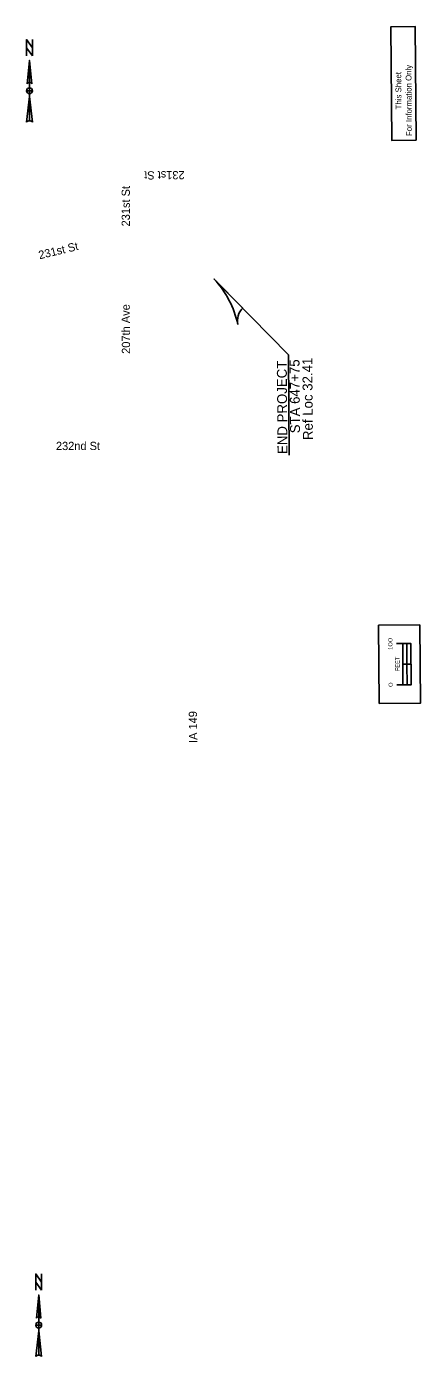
# Model space of a CAD drawing. Extents: x 23417754 to 23421386, y 6737896 to 6790956.
# Drawn here: x 23420298 to 23421255, y 6787728 to 6790956 of the extents above; entities that cross this region are included whole.
import ezdxf

# ---------------------------------------------------------------- set-up
doc = ezdxf.new("R2010")
doc.units = 0
for name, color, linetype in [('Curb', 7, 'Continuous'), ('Default', 7, 'Continuous'), ('dsnCellElements', 7, 'Continuous'), ('TextAlignmentLrg', 7, 'Continuous')]:
    doc.layers.add(name, color=color, linetype=linetype)

msp = doc.modelspace()

# ---------------------------------------------------------------- linework, layer by layer
at = {"layer": 'Curb'}
for p, q in [((23420305.1, 6790873.3), (23420310.8, 6790816.9)), ((23420305.1, 6790873.3), (23420305.1, 6790726.8)), ((23420299.5, 6790816.9), (23420299.5, 6790816.9)), ((23420299.7, 6790817.5), (23420300.8, 6790818.6)), ((23420298.1, 6790724), (23420305.1, 6790785.9)), ((23420305.1, 6790793), (23420305.1, 6790793)), ((23421231.8, 6789408.3), (23421211.8, 6789408.1)), ((23421231.8, 6789408.3), (23421211.8, 6789408.1))]:
    msp.add_line(p, q, dxfattribs=at)
for points in [[(23421185, 6790679.5), (23421182.9, 6790955.1), (23421241.9, 6790955.6), (23421244, 6790680)], [(23421244, 6790680), (23421241.9, 6790955.6), (23421182.9, 6790955.1), (23421185, 6790679.5)], [(23420312.2, 6790884.5), (23420298.1, 6790904.3), (23420298.1, 6790924), (23420312.2, 6790904.3)], [(23421154.6, 6789312.7), (23421153.1, 6789502.7), (23421253.1, 6789503.5), (23421254.6, 6789313.5)], [(23421254.6, 6789313.5), (23421154.6, 6789312.7), (23421153.1, 6789502.7), (23421253.1, 6789503.5)], [(23421221.8, 6789408.2), (23421221.4, 6789458.2), (23421211.5, 6789458.1), (23421211.8, 6789408.1)], [(23421232.2, 6789358.3), (23421231.8, 6789408.3), (23421221.8, 6789408.2), (23421222.2, 6789358.2)]]:
    msp.add_lwpolyline(points, close=True, dxfattribs=at)
for points in [[(23420298.1, 6790884.5), (23420298.1, 6790924), (23420312.2, 6790904.3), (23420312.2, 6790924)], [(23420299.5, 6790816.9), (23420305.1, 6790873.3), (23420305.1, 6790819.7)], [(23420305.1, 6790793), (23420305.1, 6790800), (23420298.1, 6790800)], [(23420312.2, 6790800), (23420305.1, 6790800), (23420305.1, 6790807.1)], [(23420305.1, 6790726.8), (23420305.1, 6790785.9), (23420312.2, 6790724)], [(23421197.2, 6789358), (23421232.2, 6789358.3), (23421231.5, 6789458.3), (23421196.5, 6789458)], [(23421212.2, 6789358.1), (23421211.5, 6789458.1)]]:
    msp.add_lwpolyline(points, dxfattribs=at)
for centre, radius, start, end in [((23420305.1, 6790812.7), 7.04, 90.0204, 143.1257), ((23420305.1, 6790812.7), 7.04, 36.8481, 90.0218), ((23420305.1, 6790800), 7.04, 90, 180), ((23420305.1, 6790800), 7.04, 180, 270), ((23420305.1, 6790800), 7.04, 0, 90), ((23420305.1, 6790800), 7.04, 270, 360), ((23420305.1, 6790716.6), 10.2, 89.9894, 133.619), ((23420305.1, 6790716.6), 10.2, 46.4021, 90.0006)]:
    msp.add_arc(centre, radius, start, end, dxfattribs=at)
at = {"layer": 'dsnCellElements'}
for p, q in [((23420823, 6790272.2), (23420753, 6790343.6)), ((23420754, 6790342.7), (23420753.6, 6790343)), ((23420823, 6790272.2), (23420823, 6790272.2))]:
    msp.add_line(p, q, dxfattribs=at)
msp.add_lwpolyline([(23420753, 6790343.6), (23420934, 6790158.8), (23420935.9, 6789915.7)], dxfattribs=at)
for centre, radius, start, end in [((23420575.2, 6790179.4), 242, 12.6979, 42.728), ((23420852.7, 6790241.9), 42.4, 134.413, 192.6983)]:
    msp.add_arc(centre, radius, start, end, dxfattribs=at)
at = {"layer": 'TextAlignmentLrg'}
for p, q in [((23420327.5, 6787877.4), (23420333.1, 6787821.1)), ((23420327.5, 6787877.4), (23420327.5, 6787730.9)), ((23420321.9, 6787821.1), (23420321.9, 6787821.1)), ((23420322.1, 6787821.6), (23420323.1, 6787822.7)), ((23420320.5, 6787728.1), (23420327.5, 6787790.1)), ((23420327.5, 6787797.1), (23420327.5, 6787797.1))]:
    msp.add_line(p, q, dxfattribs=at)
msp.add_lwpolyline([(23420334.6, 6787888.7), (23420320.5, 6787908.4), (23420320.5, 6787928.1), (23420334.6, 6787908.4)], close=True, dxfattribs=at)
for points in [[(23420320.5, 6787888.7), (23420320.5, 6787928.1), (23420334.6, 6787908.4), (23420334.6, 6787928.1)], [(23420321.9, 6787821.1), (23420327.5, 6787877.4), (23420327.5, 6787823.9)], [(23420327.5, 6787797.1), (23420327.5, 6787804.2), (23420320.5, 6787804.2)], [(23420334.6, 6787804.2), (23420327.5, 6787804.2), (23420327.5, 6787811.2)], [(23420327.5, 6787730.9), (23420327.5, 6787790.1), (23420334.6, 6787728.1)]]:
    msp.add_lwpolyline(points, dxfattribs=at)
for centre, radius, start, end in [((23420327.5, 6787816.8), 7.04, 90.0204, 143.1257), ((23420327.5, 6787816.8), 7.04, 36.8481, 90.0218), ((23420327.5, 6787804.2), 7.04, 90, 180), ((23420327.5, 6787804.2), 7.04, 180, 270), ((23420327.5, 6787804.2), 7.04, 0, 90), ((23420327.5, 6787804.2), 7.04, 270, 360), ((23420327.5, 6787720.7), 10.2, 89.9894, 133.619), ((23420327.5, 6787720.7), 10.2, 46.4021, 90.0006)]:
    msp.add_arc(centre, radius, start, end, dxfattribs=at)

# ---------------------------------------------------------------- texts
at = {"layer": 'Curb'}
for s, height, p in [('For Information Only', 14.174, (23421233.9, 6790690)), ('This Sheet', 14.17, (23421208.6, 6790754.8)), ('1OO', 10, (23421186.6, 6789443.1)), ('1OO', 10, (23421186.6, 6789443.1)), ('FEET', 10, (23421204, 6789391.1)), ('O', 10, (23421187.3, 6789353)), ('O', 10, (23421187.3, 6789353))]:
    msp.add_text(s, height=height, rotation=90.4417, dxfattribs=at).set_placement(p)
at = {"layer": 'Default'}
for s, rotation, p in [('231st St', 180.4417, (23420681.9, 6790605.1)), ('231st St', 90.0192, (23420549, 6790470.6)), ('231st St', 13.597, (23420329.8, 6790390.8)), ('207th Ave', 90.4417, (23420549.5, 6790161.4)), ('232nd St', 0.0192, (23420369.4, 6789927.8)), ('IA 149', 90.4417, (23420712.5, 6789217))]:
    msp.add_text(s, height=20, rotation=rotation, dxfattribs=at).set_placement(p)
at = {"layer": 'dsnCellElements'}
for s, height, p in [('END PROJECT', 24.007, (23420931.6, 6789918.3)), ('STA 647+75', 24.01, (23420962.2, 6789968.6)), ('Ref Loc 32.41', 24.007, (23420993.4, 6789952.2))]:
    msp.add_text(s, height=height, rotation=90.4417, dxfattribs=at).set_placement(p)

doc.saveas('drawing.dxf')
